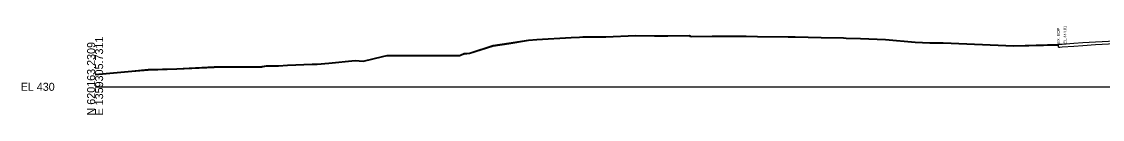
# Model space of a CAD drawing. Extents: x -26 to 803, y -27 to 3586.
# Drawn here: x -25.7 to 352.2, y 990.3 to 1021 of the extents above; entities that cross this region are included whole.
import ezdxf

# ---------------------------------------------------------------- set-up
doc = ezdxf.new("R2010")
doc.units = 0
for name, color, linetype in [('DESIGN - SHEET - Light Grid', 7, 'Continuous'), ('SURVEY - GROUND - Bottom of Topsoil Layer', 7, 'Continuous'), ('SURVEY - GROUND - Existing Pavement Layer', 7, 'Continuous'), ('SURVEY - GROUND - Existing Pavement Text', 7, 'Continuous'), ('SURVEY - GROUND - Top of Ground', 7, 'Continuous')]:
    doc.layers.add(name, color=color, linetype=linetype)

msp = doc.modelspace()

# ---------------------------------------------------------------- linework, layer by layer
at = {"layer": 'DESIGN - SHEET - Light Grid'}
msp.add_line((0, 1000), (400, 1000), dxfattribs=at)
at = {"layer": 'SURVEY - GROUND - Bottom of Topsoil Layer'}
for p, q in [((154.53, 1016.32), (166.51, 1017.07)), ((166.51, 1017.07), (169.42, 1017.21)), ((169.42, 1017.21), (170.56, 1017.24)), ((170.56, 1017.24), (171.07, 1017.27)), ((171.07, 1017.27), (178.62, 1017.25)), ((178.62, 1017.25), (188.96, 1017.71)), ((188.96, 1017.71), (195.57, 1017.63)), ((195.57, 1017.63), (196.06, 1017.65)), ((196.06, 1017.65), (200.26, 1017.68)), ((200.26, 1017.68), (207.72, 1017.73)), ((207.72, 1017.73), (208.09, 1017.57)), ((208.09, 1017.57), (208.45, 1017.41)), ((208.45, 1017.41), (215.78, 1017.51)), ((215.78, 1017.51), (217.74, 1017.52)), ((217.74, 1017.52), (227.64, 1017.48)), ((227.64, 1017.48), (231.64, 1017.41)), ((231.64, 1017.41), (242.35, 1017.26)), ((242.35, 1017.26), (244.78, 1017.26)), ((244.78, 1017.26), (253.86, 1017.07)), ((253.86, 1017.07), (261.75, 1016.89)), ((261.75, 1016.89), (262.7, 1016.84)), ((262.7, 1016.84), (267.61, 1016.72)), ((267.61, 1016.72), (276.36, 1016.32)), ((131.08, 1011.6), (139.2, 1014.2)), ((139.2, 1014.2), (144.69, 1015.01)), ((144.69, 1015.01), (151.56, 1016.11)), ((151.56, 1016.11), (154.53, 1016.32)), ((276.36, 1016.32), (286.76, 1015.43)), ((286.76, 1015.43), (291.88, 1015.24)), ((291.88, 1015.24), (296.62, 1015.18)), ((296.62, 1015.18), (321.24, 1014.15)), ((321.24, 1014.15), (336.84, 1014.56)), ((336.84, 1014.56), (336.84, 1014.81)), ((93.79, 1008.81), (100.46, 1010.4)), ((100.46, 1010.4), (102.05, 1010.74)), ((102.05, 1010.74), (107.38, 1010.74)), ((107.38, 1010.74), (124.64, 1010.8)), ((124.64, 1010.8), (126.72, 1010.8)), ((126.72, 1010.8), (127.62, 1010.81)), ((127.62, 1010.81), (127.76, 1010.85)), ((127.76, 1010.85), (129.07, 1011.42)), ((129.07, 1011.42), (131.08, 1011.6)), ((12.84, 1005.28), (18.53, 1005.84)), ((18.53, 1005.84), (28.53, 1006.15)), ((28.53, 1006.15), (41.66, 1006.77)), ((41.66, 1006.77), (45.45, 1006.8)), ((45.45, 1006.8), (58.33, 1006.89)), ((58.33, 1006.89), (59.87, 1007.22)), ((59.87, 1007.22), (63.87, 1007.19)), ((63.87, 1007.19), (64.18, 1007.19)), ((64.18, 1007.19), (67.28, 1007.39)), ((67.28, 1007.39), (75.86, 1007.75)), ((75.86, 1007.75), (77.65, 1007.79)), ((77.65, 1007.79), (81.72, 1008.14)), ((81.72, 1008.14), (90.98, 1009.04)), ((90.98, 1009.04), (93.79, 1008.81)), ((0, 1004.16), (12.84, 1005.28))]:
    msp.add_line(p, q, dxfattribs=at)
at = {"layer": 'SURVEY - GROUND - Existing Pavement Layer'}
for p, q in [((336.84, 1013.81), (336.84, 1014.81)), ((336.84, 1013.81), (337.41, 1013.85)), ((337.41, 1013.85), (338.17, 1013.9)), ((338.17, 1013.9), (342.31, 1014.17)), ((342.31, 1014.17), (345.36, 1014.39)), ((345.36, 1014.39), (349.86, 1014.7)), ((349.86, 1014.7), (356.75, 1015.06))]:
    msp.add_line(p, q, dxfattribs=at)
at = {"layer": 'SURVEY - GROUND - Top of Ground'}
msp.add_lwpolyline([(0, 1004.41), (12.84, 1005.53), (18.53, 1006.09), (28.53, 1006.4), (41.66, 1007.02), (45.45, 1007.05), (58.33, 1007.14), (59.87, 1007.47), (63.87, 1007.44), (64.18, 1007.44), (67.28, 1007.64), (75.86, 1008), (77.65, 1008.04), (81.72, 1008.39), (90.98, 1009.29), (93.79, 1009.06), (100.46, 1010.65), (102.05, 1010.99), (107.38, 1010.99), (124.64, 1011.05), (126.72, 1011.05), (127.62, 1011.06), (127.76, 1011.1), (129.07, 1011.67), (131.08, 1011.85), (139.2, 1014.45), (144.69, 1015.26), (151.56, 1016.36), (154.53, 1016.57), (166.51, 1017.32), (169.42, 1017.46), (170.56, 1017.49), (171.07, 1017.52), (178.62, 1017.5), (188.96, 1017.96), (195.57, 1017.88), (196.06, 1017.9), (200.26, 1017.93), (207.72, 1017.98), (208.09, 1017.82), (208.45, 1017.66), (215.78, 1017.76), (217.74, 1017.77), (227.64, 1017.73), (231.64, 1017.66), (242.35, 1017.51), (244.78, 1017.51), (253.86, 1017.32), (261.75, 1017.14), (262.7, 1017.09), (267.61, 1016.97), (276.36, 1016.57), (286.76, 1015.68), (291.88, 1015.49), (296.62, 1015.43), (321.24, 1014.4), (336.84, 1014.81), (337.41, 1014.85), (338.17, 1014.9), (342.31, 1015.17), (345.36, 1015.39), (349.86, 1015.7), (356.75, 1016.06)], dxfattribs=at)

# ---------------------------------------------------------------- texts
at = {"layer": 'DESIGN - SHEET - Light Grid'}
for s, p in [('E 1359305.7311', (2.8, 990)), ('N 620163.2309', (0, 990))]:
    msp.add_text(s, height=2.8, rotation=90, dxfattribs=at).set_placement(p)
msp.add_text('EL 430', height=2.8, dxfattribs=at).set_placement((-26, 998.6))
at = {"layer": 'SURVEY - GROUND - Existing Pavement Text'}
for s, p in [('EL.444.81', (339.67, 1015.01)), ('EX. EOP', (337.34, 1015.01))]:
    msp.add_text(s, height=1, rotation=90, dxfattribs=at).set_placement(p)

doc.saveas('drawing.dxf')
